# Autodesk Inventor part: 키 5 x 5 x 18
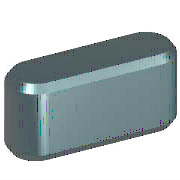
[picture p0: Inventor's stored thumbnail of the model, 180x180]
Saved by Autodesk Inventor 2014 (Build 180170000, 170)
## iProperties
IsCustomPart: 1
Created: 2012-02
Part Number: 키 5 x 5 x 18
Material: 강철, 연강
Description: 키 및 해당 키홈
Document SubType Name: Modeling
Standard: KS B 1311
Designer: mduedu
Standards Organization: KS
Language: ko-KR
Size Designation: 5 x 5 x 18
Categories: <MemberInstance><Categories><Category DisplayName="샤프트 부품" InternalName="7f7aeb1f-a693-4053-b835-cee3144e0d98" Mnemonic="SHFT"><Category DisplayName="키" Interna
Density: 1 g/cm^3
Appearance: 금색
Author: mduedu
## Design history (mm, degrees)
workplane "Work Plane1"
workplane "Work Plane2"
sketch "스케치1"
  geometry: L1 (2.5, 2.5)-(15.5, 2.5); L2 (15.5, -2.5)-(2.5, -2.5); L3 (0, 9.4)-(0, -7.4) reference; L4 (-5, 0)-(30, 0) reference; L5 (18, 0)-(18, 7); A1 r 2.5 centre (2.5, 0) between (2.5, 2.5) and (2.5, -2.5); A2 r 2.5 centre (15.5, 0) between (15.5, -2.5) and (15.5, 2.5)
  constraints: 6 end point, 5 point on circle, 4 tangent, 3 point on line, 2 centre point, 1 horizontal, 1 parallel, 1 perpendicular
  dimensions: "d0" = 2.5 radius of A1 (= 0.5 x PB); "d13" = 2.5 radius of A2 (= 0.5 x PB); "d14" = 18 distance between parallel lines of L5 L3 (= NLG)
extrude "본체1" new body sketch "스케치1" taper "d3" = 0 deg; stored distance "d4" = 10
workplane "Work Plane3"
body "Solid1"
chamfer "모따기1" distance "d8" = 0.4 (= PHH); stored, may be unused: second distance "d9" = 0.4 (= PHH), angle "d15" = 45 deg
other parameters: "d1" = -3 (= -PNT), "d2" = 2 (= PH - PNT), "NLG" = 18 [user parameter; used in 3 equation terms], "PB" = 5 [user parameter; used in 2 equation terms], "PNT" = 3 [user parameter; used in 2 equation terms], "PH" = 5 [user parameter; used in 1 equation term], "PHH" = 0.4 [user parameter; used in 2 equation terms], "d10" = 0, "d16" = 0, "d17" = 0, "d18" = 0, "WDMIN" = 12 [user parameter], "PLB2" = 18 (= NLG) [user parameter], "WDMAX" = 17 [user parameter], "PLB1" = 18 (= NLG) [user parameter], "RR" = 0.16 [user parameter], "PUEB" = 2.3 [user parameter]
